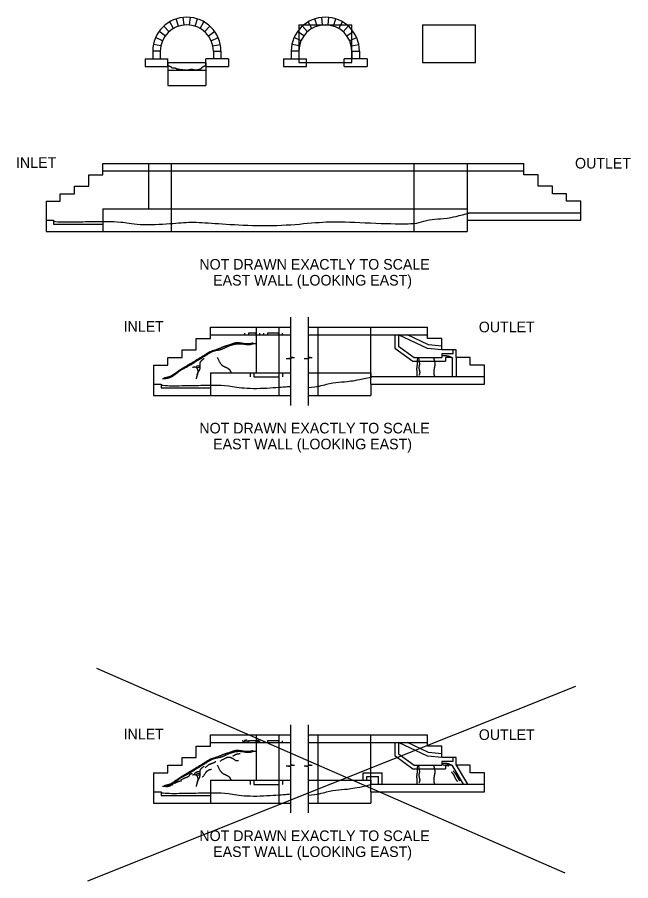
# Model space of a CAD drawing. Extents: x 21249 to 21441, y 6062 to 6293.
# Drawn here: x 21264.7 to 21345.6, y 6061.8 to 6175.7 of the extents above; entities that cross this region are included whole.
import ezdxf

# ---------------------------------------------------------------- set-up
doc = ezdxf.new("R2010")
doc.units = 0
for name, color, linetype in [('BR_P_Slab_Hidden', 7, 'Continuous'), ('BR_P_Slab_Object', 7, 'Continuous'), ('BR_P_Slab_Reinforcing', 7, 'Continuous'), ('DR_X_Culvert', 7, 'Continuous'), ('SC_Scratch1', 7, 'Continuous'), ('SC_Scratch2', 7, 'Continuous'), ('SH_Text', 7, 'Continuous'), ('XS_X_Ground_Line', 7, 'Continuous')]:
    doc.layers.add(name, color=color, linetype=linetype)

msp = doc.modelspace()

# ---------------------------------------------------------------- linework, layer by layer
at = {"layer": 'BR_P_Slab_Hidden'}
msp.add_line((21284.56, 6168.73), (21289.56, 6168.73), dxfattribs=at)
at = {"layer": 'BR_P_Slab_Object'}
for p, q in [((21284.56, 6169.73), (21289.56, 6169.73)), ((21284.56, 6169.73), (21284.56, 6166.73)), ((21289.56, 6169.73), (21289.56, 6166.73)), ((21284.56, 6166.73), (21289.56, 6166.73))]:
    msp.add_line(p, q, dxfattribs=at)
at = {"layer": 'BR_P_Slab_Reinforcing'}
for p, q in [((21275.13, 6089.88), (21336.88, 6062.87)), ((21273.99, 6061.85), (21338.36, 6087.49))]:
    msp.add_line(p, q, dxfattribs=at)
at = {"layer": 'DR_X_Culvert'}
for p, q in [((21286.69, 6174.69), (21286.58, 6175.68)), ((21287.43, 6174.69), (21287.54, 6175.68)), ((21304.95, 6174.69), (21304.84, 6175.68)), ((21305.7, 6174.69), (21305.8, 6175.68)), ((21284.71, 6173.8), (21284.04, 6174.54)), ((21285.3, 6174.23), (21284.8, 6175.1)), ((21285.97, 6174.53), (21285.66, 6175.48)), ((21288.15, 6174.53), (21288.46, 6175.48)), ((21288.82, 6174.23), (21289.32, 6175.1)), ((21289.41, 6173.8), (21290.08, 6174.54)), ((21301.82, 6174.73), (21308.82, 6174.73)), ((21301.82, 6174.73), (21301.82, 6169.73)), ((21302.97, 6173.8), (21302.3, 6174.54)), ((21303.56, 6174.23), (21303.06, 6175.1)), ((21304.23, 6174.53), (21303.92, 6175.48)), ((21306.41, 6174.53), (21306.72, 6175.48)), ((21307.08, 6174.23), (21307.58, 6175.1)), ((21307.67, 6173.8), (21308.34, 6174.54)), ((21308.82, 6169.73), (21308.82, 6174.73)), ((21318.12, 6174.73), (21318.12, 6169.73)), ((21318.12, 6174.73), (21325.12, 6174.73)), ((21325.12, 6169.73), (21325.12, 6174.73)), ((21284.22, 6173.26), (21283.41, 6173.84)), ((21289.9, 6173.26), (21290.71, 6173.84)), ((21302.48, 6173.26), (21301.67, 6173.84)), ((21308.16, 6173.26), (21308.97, 6173.84)), ((21283.86, 6172.62), (21282.94, 6173.03)), ((21290.26, 6172.62), (21291.18, 6173.03)), ((21302.12, 6172.62), (21301.21, 6173.03)), ((21308.52, 6172.62), (21309.44, 6173.03)), ((21283.56, 6171.23), (21282.56, 6171.23)), ((21282.56, 6171.23), (21282.56, 6170.23)), ((21283.63, 6171.93), (21282.66, 6172.13)), ((21283.56, 6171.23), (21283.56, 6170.23)), ((21290.49, 6171.93), (21291.46, 6172.13)), ((21290.56, 6171.23), (21290.56, 6170.23)), ((21290.56, 6171.23), (21291.56, 6171.23)), ((21291.56, 6171.23), (21291.56, 6170.23)), ((21301.82, 6171.23), (21300.82, 6171.23)), ((21300.82, 6171.23), (21300.82, 6170.23)), ((21301.9, 6171.93), (21300.92, 6172.13)), ((21301.82, 6171.23), (21301.82, 6170.23)), ((21308.75, 6171.93), (21309.72, 6172.13)), ((21308.82, 6171.23), (21308.82, 6170.23)), ((21308.82, 6171.23), (21309.82, 6171.23)), ((21309.82, 6171.23), (21309.82, 6170.23)), ((21281.56, 6170.23), (21284.56, 6170.23)), ((21281.56, 6170.23), (21281.56, 6169.23)), ((21284.56, 6169.23), (21284.56, 6170.23)), ((21292.56, 6170.23), (21289.56, 6170.23)), ((21289.56, 6169.23), (21289.56, 6170.23)), ((21292.56, 6170.23), (21292.56, 6169.23)), ((21299.82, 6170.23), (21302.82, 6170.23)), ((21299.82, 6170.23), (21299.82, 6169.23)), ((21302.82, 6169.23), (21302.82, 6170.23)), ((21310.82, 6170.23), (21307.82, 6170.23)), ((21307.82, 6169.23), (21307.82, 6170.23)), ((21310.82, 6170.23), (21310.82, 6169.23)), ((21281.56, 6169.23), (21284.56, 6169.23)), ((21289.56, 6169.23), (21292.56, 6169.23)), ((21299.82, 6169.23), (21302.82, 6169.23)), ((21301.82, 6169.73), (21308.82, 6169.73)), ((21307.82, 6169.23), (21310.82, 6169.23)), ((21318.12, 6169.73), (21325.12, 6169.73)), ((21276, 6156.44), (21331.5, 6156.44)), ((21276, 6154.94), (21276, 6156.44)), ((21282, 6156.44), (21282, 6150.44)), ((21285, 6156.44), (21285, 6147.44)), ((21285, 6156.44), (21285, 6147.44)), ((21317, 6156.44), (21317, 6147.44)), ((21324, 6156.44), (21324, 6147.44)), ((21324, 6156.44), (21324, 6148.94)), ((21331.5, 6154.94), (21331.5, 6156.44)), ((21276, 6155.44), (21331.5, 6155.44)), ((21274.12, 6153.44), (21274.12, 6154.94)), ((21274.12, 6154.94), (21276, 6154.94)), ((21333.37, 6154.94), (21331.5, 6154.94)), ((21333.37, 6153.44), (21333.37, 6154.94)), ((21272.25, 6152.44), (21272.25, 6153.44)), ((21272.25, 6153.44), (21274.12, 6153.44)), ((21335.25, 6153.44), (21333.37, 6153.44)), ((21335.25, 6152.44), (21335.25, 6153.44)), ((21270.37, 6151.44), (21270.37, 6152.44)), ((21270.37, 6152.44), (21272.25, 6152.44)), ((21337.12, 6152.44), (21335.25, 6152.44)), ((21337.12, 6151.44), (21337.12, 6152.44)), ((21268.5, 6151.44), (21268.5, 6147.44)), ((21268.5, 6151.44), (21270.37, 6151.44)), ((21339, 6151.44), (21337.12, 6151.44)), ((21339, 6148.94), (21339, 6151.44)), ((21276, 6150.44), (21324, 6150.44)), ((21276, 6150.44), (21276, 6147.44)), ((21324, 6150.44), (21324, 6149.94)), ((21324, 6149.94), (21339, 6149.94)), ((21268.5, 6148.94), (21269.5, 6148.94)), ((21269.5, 6148.94), (21269.5, 6148.44)), ((21269.5, 6148.44), (21276, 6148.44)), ((21324, 6148.94), (21339, 6148.94)), ((21324, 6148.94), (21324, 6147.44)), ((21268.5, 6147.44), (21324, 6147.44)), ((21290.18, 6134.84), (21300.72, 6134.84)), ((21290.18, 6133.34), (21290.18, 6134.84)), ((21296.18, 6134.84), (21296.18, 6128.84)), ((21299.18, 6134.84), (21299.18, 6125.84)), ((21303.05, 6134.84), (21318.81, 6134.84)), ((21304.31, 6134.84), (21304.31, 6125.84)), ((21311.31, 6127.34), (21311.31, 6134.84)), ((21318.81, 6133.34), (21318.81, 6134.84)), ((21290.18, 6133.84), (21300.72, 6133.84)), ((21303.05, 6133.84), (21318.81, 6133.84)), ((21288.31, 6131.84), (21288.31, 6133.34)), ((21288.31, 6133.34), (21290.18, 6133.34)), ((21320.68, 6133.34), (21318.81, 6133.34)), ((21320.68, 6131.84), (21320.68, 6133.34)), ((21286.43, 6130.84), (21286.43, 6131.84)), ((21286.43, 6131.84), (21288.31, 6131.84)), ((21322.56, 6131.84), (21320.68, 6131.84)), ((21322.56, 6130.84), (21322.56, 6131.84)), ((21284.56, 6129.84), (21284.56, 6130.84)), ((21284.56, 6130.84), (21286.43, 6130.84)), ((21324.43, 6130.84), (21322.56, 6130.84)), ((21324.43, 6129.84), (21324.43, 6130.84)), ((21282.68, 6129.84), (21282.68, 6125.84)), ((21282.68, 6129.84), (21284.56, 6129.84)), ((21326.31, 6129.84), (21324.43, 6129.84)), ((21326.31, 6127.34), (21326.31, 6129.84)), ((21290.18, 6128.84), (21300.72, 6128.84)), ((21290.18, 6128.84), (21290.18, 6125.84)), ((21303.05, 6128.84), (21311.31, 6128.84)), ((21311.31, 6128.84), (21311.31, 6128.34)), ((21311.31, 6128.34), (21326.31, 6128.34)), ((21282.68, 6127.34), (21283.68, 6127.34)), ((21283.68, 6127.34), (21283.68, 6126.85)), ((21283.68, 6126.84), (21290.18, 6126.84)), ((21311.31, 6127.34), (21326.31, 6127.34)), ((21311.31, 6127.34), (21311.31, 6125.84)), ((21282.68, 6125.84), (21300.72, 6125.84)), ((21303.05, 6125.84), (21311.31, 6125.84)), ((21290.18, 6081.09), (21300.72, 6081.09)), ((21290.18, 6079.59), (21290.18, 6081.09)), ((21290.18, 6080.09), (21300.72, 6080.09)), ((21296.18, 6081.09), (21296.18, 6075.09)), ((21299.18, 6081.09), (21299.18, 6072.09)), ((21303.05, 6081.09), (21318.81, 6081.09)), ((21303.05, 6080.09), (21318.81, 6080.09)), ((21304.31, 6081.09), (21304.31, 6072.09)), ((21311.31, 6073.59), (21311.31, 6081.09)), ((21318.81, 6079.59), (21318.81, 6081.09)), ((21288.31, 6078.09), (21288.31, 6079.59)), ((21288.31, 6079.59), (21290.18, 6079.59)), ((21320.68, 6079.59), (21318.81, 6079.59)), ((21320.68, 6078.09), (21320.68, 6079.59)), ((21286.43, 6077.09), (21286.43, 6078.09)), ((21286.43, 6078.09), (21288.31, 6078.09)), ((21322.56, 6078.09), (21320.68, 6078.09)), ((21322.56, 6077.09), (21322.56, 6078.09)), ((21284.56, 6076.09), (21284.56, 6077.09)), ((21284.56, 6077.09), (21286.43, 6077.09)), ((21324.43, 6077.09), (21322.56, 6077.09)), ((21324.43, 6076.09), (21324.43, 6077.09)), ((21282.68, 6076.09), (21282.68, 6072.09)), ((21282.68, 6076.09), (21284.56, 6076.09)), ((21326.31, 6076.09), (21324.43, 6076.09)), ((21326.31, 6073.59), (21326.31, 6076.09)), ((21290.18, 6075.09), (21300.72, 6075.09)), ((21290.18, 6075.09), (21290.18, 6072.09)), ((21303.05, 6075.09), (21311.31, 6075.09)), ((21311.31, 6075.09), (21311.31, 6074.59)), ((21311.31, 6074.59), (21326.31, 6074.59)), ((21282.68, 6073.59), (21283.68, 6073.59)), ((21283.68, 6073.59), (21283.68, 6073.09)), ((21311.31, 6073.59), (21326.31, 6073.59)), ((21311.31, 6073.59), (21311.31, 6072.09)), ((21282.68, 6072.09), (21300.72, 6072.09)), ((21283.68, 6073.09), (21290.18, 6073.09)), ((21303.05, 6072.09), (21311.31, 6072.09))]:
    msp.add_line(p, q, dxfattribs=at)
for centre in [(21288.53, 6129.64), (21288.53, 6075.88)]:
    msp.add_circle(centre, 0.167, dxfattribs=at)
for centre, radius in [((21287.06, 6171.21), 4.5), ((21305.32, 6171.21), 4.5), ((21287.06, 6171.21), 3.5), ((21305.32, 6171.21), 3.5)]:
    msp.add_arc(centre, radius, 0.4626, 179.5374, dxfattribs=at)
for points in [[(21283.85, 6128.07), (21284.57, 6128.07), (21285.38, 6128.48), (21286.12, 6129.12), (21287.43, 6129.78), (21288.34, 6130.38), (21289.61, 6131.16), (21290.54, 6131.74), (21291.67, 6131.9), (21292.73, 6132.45), (21293.89, 6132.73), (21295.29, 6132.49), (21295.91, 6132.74), (21296.18, 6132.67)], [(21284.09, 6128.17), (21284.77, 6128.31), (21285.17, 6128.52), (21285.97, 6129.1), (21286.87, 6129.66), (21288.11, 6130.39), (21289.25, 6131.09), (21290.13, 6131.65), (21290.87, 6131.85), (21292.07, 6132.35), (21292.76, 6132.53), (21293.35, 6132.81), (21294.06, 6132.81), (21294.56, 6132.68), (21295.4, 6132.68), (21295.65, 6132.75), (21295.82, 6132.78)], [(21288.43, 6128.54), (21288.49, 6128.85), (21288.8, 6129.22), (21288.8, 6129.73), (21288.8, 6130.17), (21289.04, 6130.5), (21289.33, 6130.7)], [(21291.06, 6130.9), (21291.37, 6130.17), (21291.8, 6129.71), (21292.43, 6129.48), (21292.75, 6129.2), (21292.89, 6128.84)], [(21317.45, 6130.84), (21317.45, 6130.01), (21317.33, 6129.36), (21317.41, 6128.88), (21317.37, 6128.34)], [(21317.58, 6130.84), (21317.76, 6130.02), (21317.66, 6129.72), (21317.66, 6129.3), (21317.81, 6128.81), (21317.66, 6128.51)], [(21319.56, 6130.84), (21319.82, 6130.15), (21319.67, 6129.4), (21319.56, 6128.68), (21319.74, 6128.34)], [(21320.68, 6131.11), (21321.42, 6131.11), (21321.89, 6130.9), (21322.11, 6130.77)], [(21287.82, 6129.57), (21288.21, 6129.65), (21288.44, 6129.37), (21288.55, 6128.94), (21288.4, 6128.43), (21288.27, 6128.03)], [(21294.82, 6080.09), (21294.63, 6080.15), (21294.42, 6080.24), (21294.42, 6080.3)], [(21295.15, 6080.09), (21295, 6080.22), (21295, 6080.42), (21294.63, 6080.31)], [(21296.27, 6080.09), (21296.35, 6080.27), (21296.46, 6080.37), (21296.46, 6080.42)], [(21296.34, 6080.09), (21296.45, 6080.18), (21296.58, 6080.25), (21296.58, 6080.35)], [(21283.85, 6074.32), (21284.57, 6074.32), (21285.38, 6074.73), (21286.12, 6075.37), (21287.43, 6076.03), (21288.34, 6076.63), (21289.61, 6077.41), (21290.54, 6077.98), (21291.67, 6078.15), (21292.73, 6078.69), (21293.89, 6078.98), (21295.29, 6078.73), (21295.91, 6078.98), (21296.18, 6078.92)], [(21284.09, 6074.41), (21284.77, 6074.55), (21285.17, 6074.77), (21285.97, 6075.35), (21286.87, 6075.91), (21288.11, 6076.63), (21289.25, 6077.34), (21290.13, 6077.9), (21290.87, 6078.1), (21292.07, 6078.6), (21292.76, 6078.78), (21293.35, 6079.05), (21294.06, 6079.05), (21294.56, 6078.93), (21295.4, 6078.93), (21295.65, 6079), (21295.82, 6079.02)], [(21291.46, 6077.63), (21292.01, 6077.97), (21292.62, 6078.2), (21293.15, 6077.97), (21293.49, 6077.7), (21293.63, 6077.7), (21293.88, 6077.7)], [(21293.15, 6078.29), (21293.38, 6078.47), (21293.85, 6078.61), (21294.11, 6078.61)], [(21288.43, 6074.79), (21288.49, 6075.09), (21288.8, 6075.47), (21288.8, 6075.98), (21288.8, 6076.42), (21289.04, 6076.74), (21289.33, 6076.95)], [(21289.47, 6076.75), (21289.94, 6077.2), (21290.63, 6077.4), (21290.89, 6077.59)], [(21291.06, 6077.15), (21291.37, 6076.42), (21291.8, 6075.96), (21292.43, 6075.73), (21292.75, 6075.45), (21292.89, 6075.09)], [(21317.45, 6077.09), (21317.45, 6076.26), (21317.33, 6075.6), (21317.41, 6075.13), (21317.37, 6074.59)], [(21317.58, 6077.09), (21317.76, 6076.27), (21317.66, 6075.97), (21317.66, 6075.55), (21317.81, 6075.06), (21317.66, 6074.76)], [(21319.56, 6077.09), (21319.82, 6076.39), (21319.67, 6075.65), (21319.56, 6074.93), (21319.74, 6074.59)], [(21320.68, 6077.36), (21321.42, 6077.36), (21321.89, 6077.15), (21322.11, 6077.01)], [(21320.68, 6077.19), (21321.12, 6077.07), (21321.41, 6077.07), (21321.61, 6076.99)], [(21286.27, 6075.15), (21286.82, 6075.43), (21287.41, 6075.63), (21287.41, 6075.9), (21287.78, 6076.01)], [(21287.82, 6075.82), (21288.21, 6075.9), (21288.44, 6075.62), (21288.55, 6075.19), (21288.4, 6074.68), (21288.27, 6074.28)], [(21288.08, 6075.98), (21288.31, 6076.19), (21288.55, 6076.27), (21288.68, 6076.27)], [(21289.14, 6075.51), (21289.5, 6076.01), (21289.7, 6076.32), (21290.11, 6076.54), (21290.29, 6076.54)], [(21321.94, 6076.19), (21322.23, 6075.87), (21322.39, 6075.45), (21322.56, 6075.15), (21322.75, 6074.96)], [(21322.16, 6076.34), (21322.48, 6075.96), (21322.68, 6075.57), (21322.86, 6075.3), (21323, 6075.03)], [(21284.3, 6074.26), (21284.61, 6074.3), (21284.88, 6074.39), (21285.09, 6074.53), (21285.27, 6074.53)], [(21285.38, 6074.67), (21285.73, 6074.84), (21286.03, 6075), (21286.27, 6075), (21286.37, 6075)]]:
    msp.add_open_spline(points, degree=2, dxfattribs=at)
at = {"layer": 'SC_Scratch1'}
for p, q in [((21296.18, 6134.04), (21295.18, 6134.04)), ((21295.18, 6134.04), (21295.18, 6133.84)), ((21296.18, 6133.84), (21296.18, 6134.04)), ((21299.18, 6134.04), (21297.68, 6134.04)), ((21297.68, 6134.04), (21297.68, 6133.84)), ((21299.18, 6133.84), (21299.18, 6134.04)), ((21314.98, 6133.84), (21314.98, 6132.34)), ((21318.81, 6132.01), (21314.98, 6133.84)), ((21314.98, 6132.34), (21317.02, 6130.84)), ((21320.68, 6131.84), (21318.81, 6132.01)), ((21322.18, 6131.34), (21320.68, 6131.34)), ((21320.68, 6131.34), (21320.68, 6130.84)), ((21322.18, 6131.34), (21322.18, 6131.84)), ((21317.02, 6130.84), (21320.68, 6130.84)), ((21322.06, 6130.84), (21322.06, 6128.34)), ((21322.56, 6130.84), (21322.56, 6128.34)), ((21295.91, 6128.84), (21295.91, 6128.28)), ((21295.91, 6128.28), (21299.18, 6128.28)), ((21299.18, 6128.84), (21299.18, 6128.28)), ((21296.18, 6080.29), (21295.18, 6080.29)), ((21295.18, 6080.29), (21295.18, 6080.09)), ((21296.18, 6080.09), (21296.18, 6080.29)), ((21299.18, 6080.29), (21297.68, 6080.29)), ((21297.68, 6080.29), (21297.68, 6080.09)), ((21299.18, 6080.09), (21299.18, 6080.29)), ((21314.98, 6080.09), (21314.98, 6078.59)), ((21318.81, 6078.26), (21314.98, 6080.09)), ((21314.98, 6078.59), (21317.02, 6077.09)), ((21320.68, 6078.09), (21318.81, 6078.26)), ((21322.18, 6077.59), (21322.18, 6078.09)), ((21317.02, 6077.09), (21320.68, 6077.09)), ((21322.18, 6077.59), (21320.68, 6077.59)), ((21320.68, 6077.59), (21320.68, 6077.09)), ((21322.56, 6077.09), (21324.06, 6074.59)), ((21310.81, 6075.59), (21312.31, 6075.59)), ((21310.81, 6075.09), (21310.81, 6075.59)), ((21312.31, 6074.59), (21312.31, 6075.59)), ((21295.91, 6075.09), (21295.91, 6074.53)), ((21295.91, 6074.53), (21299.18, 6074.53)), ((21299.18, 6075.09), (21299.18, 6074.53))]:
    msp.add_line(p, q, dxfattribs=at)
at = {"layer": 'SC_Scratch2'}
for p, q in [((21294.68, 6134.04), (21294.68, 6133.84)), ((21296.68, 6133.84), (21296.68, 6134.04)), ((21297.18, 6134.04), (21297.18, 6133.84)), ((21299.68, 6133.84), (21299.68, 6134.04)), ((21314.48, 6133.84), (21314.48, 6132.09)), ((21318.94, 6132.5), (21316.13, 6133.84)), ((21320.68, 6132.34), (21318.94, 6132.5)), ((21314.48, 6132.09), (21316.85, 6130.34)), ((21316.85, 6130.34), (21321.18, 6130.34)), ((21322.06, 6130.84), (21321.18, 6130.84)), ((21321.18, 6130.84), (21321.18, 6130.34)), ((21295.41, 6128.84), (21295.41, 6128.28)), ((21299.68, 6128.84), (21299.68, 6128.28)), ((21294.68, 6080.29), (21294.68, 6080.09)), ((21296.68, 6080.09), (21296.68, 6080.29)), ((21297.18, 6080.29), (21297.18, 6080.09)), ((21299.68, 6080.09), (21299.68, 6080.29)), ((21314.48, 6080.09), (21314.48, 6078.34)), ((21318.94, 6078.75), (21316.13, 6080.09)), ((21314.48, 6078.34), (21316.85, 6076.59)), ((21320.68, 6078.59), (21318.94, 6078.75)), ((21321.98, 6077.09), (21321.18, 6077.09)), ((21321.18, 6077.09), (21321.18, 6076.59)), ((21321.98, 6077.09), (21323.48, 6074.59)), ((21310.31, 6075.09), (21310.31, 6076.09)), ((21310.31, 6076.09), (21312.81, 6076.09)), ((21312.81, 6074.59), (21312.81, 6076.09)), ((21316.85, 6076.59), (21321.18, 6076.59)), ((21295.41, 6075.09), (21295.41, 6074.53)), ((21299.68, 6075.09), (21299.68, 6074.53))]:
    msp.add_line(p, q, dxfattribs=at)
at = {"layer": 'SH_Text'}
for p, q in [((21300.72, 6136.15), (21300.72, 6130.92)), ((21303.05, 6136.15), (21303.05, 6130.92)), ((21300.17, 6130.73), (21301.27, 6130.86)), ((21300.17, 6130.73), (21300.72, 6130.67)), ((21300.72, 6130.92), (21301.27, 6130.86)), ((21300.72, 6130.67), (21300.72, 6124.53)), ((21302.51, 6130.73), (21303.6, 6130.86)), ((21302.51, 6130.73), (21303.05, 6130.67)), ((21303.05, 6130.92), (21303.6, 6130.86)), ((21303.05, 6130.67), (21303.05, 6124.53)), ((21300.72, 6082.4), (21300.72, 6077.17)), ((21303.05, 6082.4), (21303.05, 6077.17)), ((21300.17, 6076.98), (21301.27, 6077.1)), ((21300.17, 6076.98), (21300.72, 6076.92)), ((21300.72, 6077.17), (21301.27, 6077.1)), ((21300.72, 6076.92), (21300.72, 6070.78)), ((21302.51, 6076.98), (21303.6, 6077.1)), ((21302.51, 6076.98), (21303.05, 6076.92)), ((21303.05, 6077.17), (21303.6, 6077.1)), ((21303.05, 6076.92), (21303.05, 6070.78))]:
    msp.add_line(p, q, dxfattribs=at)
at = {"layer": 'XS_X_Ground_Line'}
for points, degree in [([(21284.56, 6169.32), (21284.91, 6169.26), (21285.09, 6169), (21285.48, 6169.09), (21285.75, 6168.88), (21286.54, 6168.79), (21287.07, 6168.73), (21287.7, 6168.89), (21288.23, 6168.73), (21288.95, 6168.91), (21289.19, 6169.27), (21289.56, 6169.31)], 2), ([(21317, 6148.51), (21317.58, 6148.55), (21318.17, 6148.85), (21319.82, 6149.13), (21321.19, 6149.15), (21322.86, 6149.5), (21324.44, 6149.94)], 3), ([(21269.5, 6148.81), (21270.2, 6148.71), (21271.7, 6148.71), (21275.03, 6148.79), (21276.53, 6148.79), (21278.27, 6148.79), (21280.53, 6148.27), (21285.2, 6148.49), (21287.49, 6148.77), (21290.53, 6148.54), (21294.93, 6148.23), (21300.33, 6148.23), (21304.66, 6148.75), (21308.02, 6148.75), (21314.53, 6148.42), (21316.53, 6148.49), (21317, 6148.51)], 3), ([(21303.05, 6126.88), (21304.31, 6126.96), (21305.48, 6127.36), (21307.14, 6127.64), (21308.51, 6127.66), (21310.18, 6128.01), (21311.64, 6128.34)], 3), ([(21283.68, 6127.21), (21284.39, 6127.11), (21285.89, 6127.11), (21289.22, 6127.19), (21290.72, 6127.19), (21292.45, 6127.19), (21294.72, 6126.68), (21298.74, 6126.86), (21300.21, 6127), (21300.72, 6127.04)], 3), ([(21303.05, 6073.12), (21304.31, 6073.21), (21305.48, 6073.61), (21307.14, 6073.89), (21308.51, 6073.91), (21310.18, 6074.26), (21311.64, 6074.59)], 3), ([(21283.68, 6073.46), (21284.39, 6073.36), (21285.89, 6073.36), (21289.22, 6073.44), (21290.72, 6073.44), (21292.45, 6073.44), (21294.72, 6072.92), (21298.74, 6073.11), (21300.21, 6073.25), (21300.72, 6073.29)], 3)]:
    msp.add_open_spline(points, degree=degree, dxfattribs=at)

# ---------------------------------------------------------------- texts
at = {"layer": 'SC_Scratch1'}
for s, p in [('INLET', (21264.53, 6155.84)), ('OUTLET', (21338.24, 6155.76)), ('NOT DRAWN EXACTLY TO SCALE', (21288.71, 6142.43)), ('EAST WALL (LOOKING EAST)', (21290.53, 6140.33)), ('INLET', (21278.72, 6134.24)), ('OUTLET', (21325.55, 6134.17)), ('NOT DRAWN EXACTLY TO SCALE', (21288.71, 6120.83)), ('EAST WALL (LOOKING EAST)', (21290.53, 6118.73)), ('INLET', (21278.72, 6080.49)), ('OUTLET', (21325.55, 6080.41)), ('NOT DRAWN EXACTLY TO SCALE', (21288.71, 6067.08)), ('EAST WALL (LOOKING EAST)', (21290.53, 6064.98))]:
    msp.add_text(s, height=1.4, dxfattribs=at).set_placement(p)

doc.saveas('drawing.dxf')
